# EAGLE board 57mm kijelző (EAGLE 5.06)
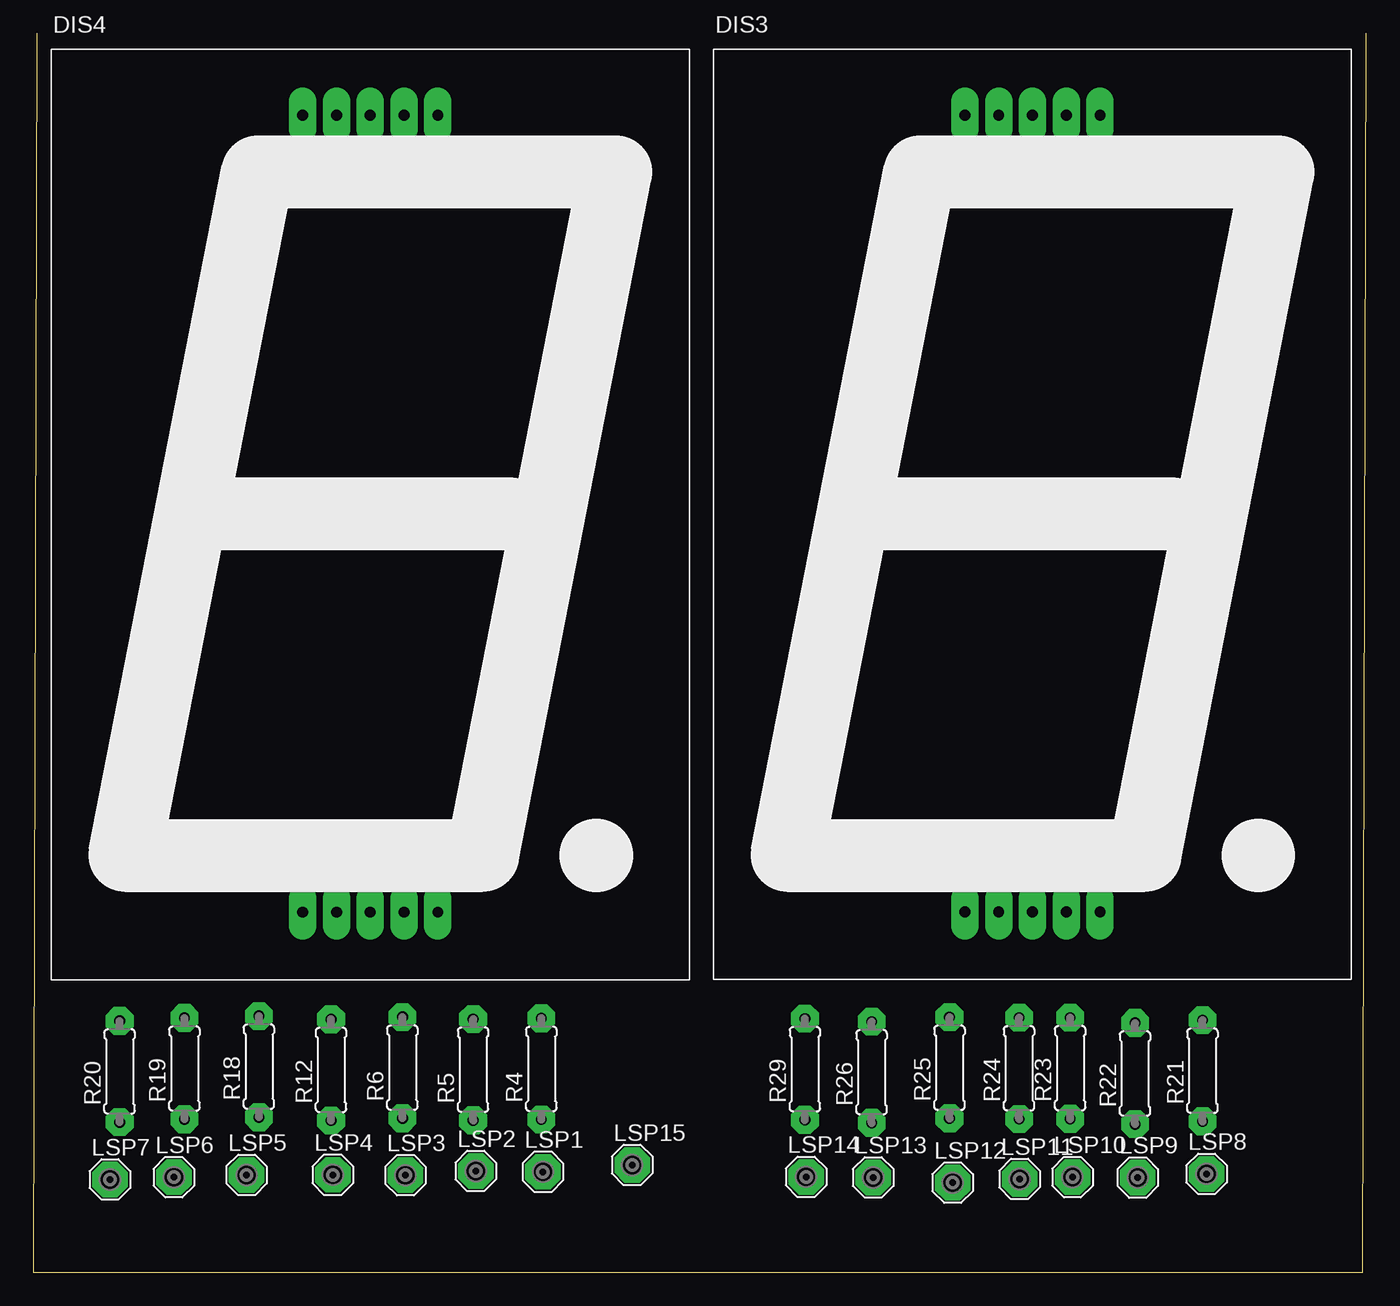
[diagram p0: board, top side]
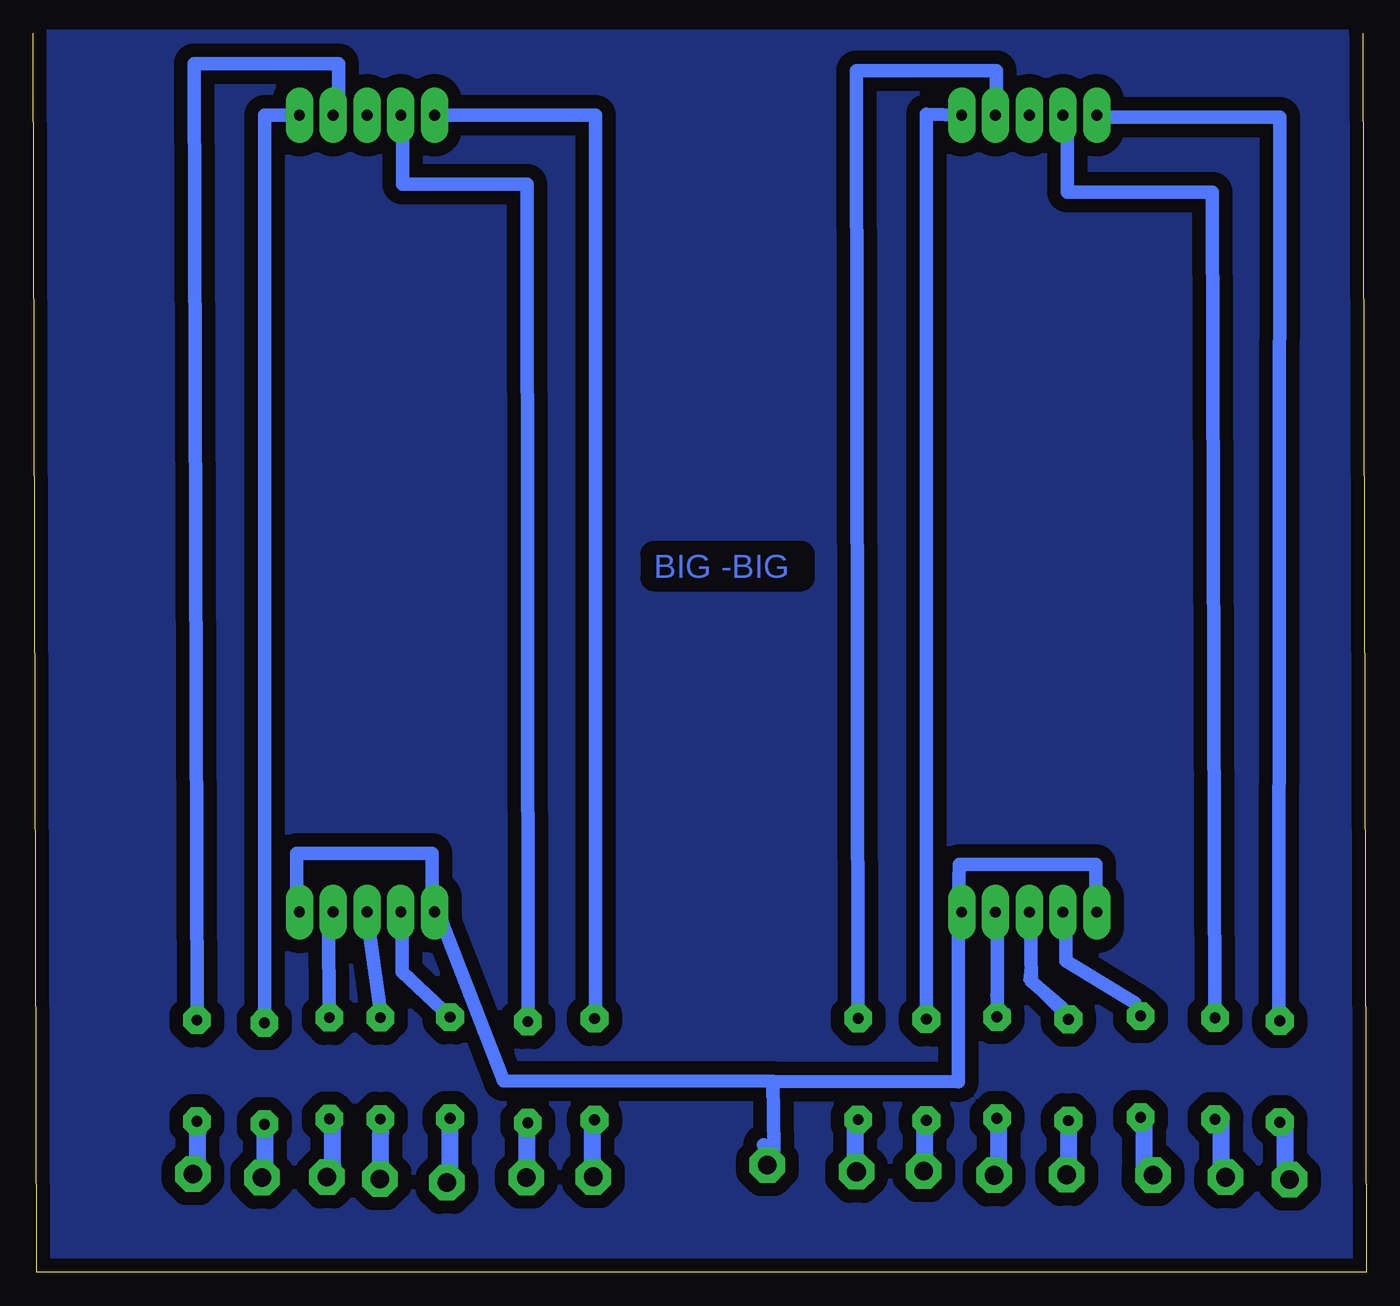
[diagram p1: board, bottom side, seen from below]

Size 100.27 x 93.21 mm. Coordinates in mm from the lower left corner, seen from the top.
Outline: 100.27,93.21 100,0 0,0 0.27,93.21
Copper layers (1*16): Top 0.035mm / dielectric 1.5mm / Bottom 0.035mm
Design rules "default *": minimum track width 10mil, minimum drill 10mil, track to track 40mil, track to pad 40mil, pad to pad 40mil, via to via 40mil, smd to smd 8mil, copper to edge 40mil, drill to drill 8mil, minimum pad ring 25mil, minimum via ring 8mil, stop-mask expansion 4mil, vias tented up to drill 0mil, thermal gap 10mil

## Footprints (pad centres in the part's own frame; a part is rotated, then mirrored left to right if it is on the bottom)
SX23-XX = drill 0.813 long: 1 18.923,5.08; 2 21.463,5.08; 3 24.003,5.08; 4 26.543,5.08; 5 29.083,5.08; 6 29.083,65.024; 7 26.543,65.024; 8 24.003,65.024; 9 21.463,65.024; 10 18.923,65.024
SE14 = drill 1.397 pad 2.54 octagon: MP 0,0
0207/7 = drill 0.813 octagon: 1 -3.81,0; 2 3.81,0

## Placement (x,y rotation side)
DIS3  SA23-11  [SX23-XX]  51.16,22.03 0 top
DIS4  SA23-11  [SX23-XX]  1.35,22.03 0 top
LSP1  SE14  [SE14]  38.35,7.57 0 top
LSP2  SE14  [SE14]  33.29,7.63 0 top
LSP3  SE14  [SE14]  28,7.31 0 top
LSP4  SE14  [SE14]  22.53,7.34 0 top
LSP5  SE14  [SE14]  16.05,7.34 0 top
LSP6  SE14  [SE14]  10.58,7.16 0 top
LSP7  SE14  [SE14]  5.77,6.99 0 top
LSP8  SE14  [SE14]  88.26,7.41 0 top
LSP9  SE14  [SE14]  83.08,7.14 0 top
LSP10  SE14  [SE14]  78.17,7.17 0 top
LSP11  SE14  [SE14]  74.19,7.03 0 top
LSP12  SE14  [SE14]  69.16,6.75 0 top
LSP13  SE14  [SE14]  63.18,7.15 0 top
LSP14  SE14  [SE14]  58.13,7.19 0 top
LSP15  SE14  [SE14]  45.04,8.08 0 top
R4  [0207/7]  38.22,15.31 90 top
R5  [0207/7]  33.09,15.25 90 top
R6  [0207/7]  27.77,15.41 90 top
R12  [0207/7]  22.4,15.23 90 top
R18  [0207/7]  16.98,15.48 90 top
R19  [0207/7]  11.38,15.33 90 top
R20  [0207/7]  6.5,15.11 90 top
R21  [0207/7]  87.95,15.17 90 top
R22  [0207/7]  82.88,14.96 90 top
R23  [0207/7]  78,15.36 90 top
R24  [0207/7]  74.15,15.35 90 top
R25  [0207/7]  68.92,15.4 90 top
R26  [0207/7]  63.06,15.06 90 top
R29  [0207/7]  58.04,15.29 90 top

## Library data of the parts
DIS3 DIS4 = display-kingbright
LSP1-LSP15 = solpad
R4-R6 R12 R18-R26 R29 = rcl

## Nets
N$1: LSP1.MP R4.1
N$3: DIS4.8
N$4: DIS3.8
N$5: LSP2.MP R5.1
N$6: LSP3.MP R6.1
N$7: LSP4.MP R12.1
N$8: DIS3.3 R24.2
N$10: LSP5.MP R18.1
N$11: LSP6.MP R19.1
N$12: DIS4.6 R5.2
N$13: LSP7.MP R20.1
N$14: LSP8.MP R21.1
N$15: LSP9.MP R22.1
N$16: LSP10.MP R23.1
N$17: LSP11.MP R24.1
N$22: LSP12.MP R25.1
N$23: LSP13.MP R26.1
N$24: DIS3.2 R25.2
N$25: DIS3.9 R26.2
N$26: LSP14.MP R29.1
N$27: DIS3.1 DIS3.5 DIS4.1 DIS4.5 LSP15.MP
N$30: DIS3.10 R29.2
N$31: DIS4.7 R4.2
N$33: DIS4.3 R12.2
N$37: DIS4.2 R18.2
N$39: DIS4.9 R19.2
N$42: DIS4.4 R6.2
N$44: DIS4.10 R20.2
N$46: DIS3.6 R22.2
N$48: DIS3.4 R23.2
N$83: DIS3.7 R21.2

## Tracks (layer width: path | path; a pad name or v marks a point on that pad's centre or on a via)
N$1
  Bottom 0.254: 38.41,11.67 38.37,11.79 R4.1 | LSP1.MP 38.41,7.86
  Bottom 1.27: 38.41,7.86 38.41,11.67
N$2
  pour Bottom: 30.73,82.92 24.72,82.79 24.6,78.59 19.8,78.59 19.93,76.78 19.98,76.21 20.02,34.29 29.9,34.29 29.9,34.03 30.43,34.03
N$5
  Bottom 0.254: 33.21,11.48 33.29,11.79 R5.1 | LSP2.MP 33.21,7.67
  Bottom 1.27: 33.21,7.67 33.21,11.48
N$6
  Bottom 0.254: 27.65,11.61 R6.1 | LSP3.MP 27.65,7.8
  Bottom 1.27: 27.65,7.8 27.65,11.61
N$7
  Bottom 0.254: 22.38,11.3 R12.1 | LSP4.MP 22.38,7.48
  Bottom 1.27: 22.38,7.48 22.38,11.3
N$8
  Bottom 0.254: R24.2 74.14,19.56 | 75.2,27.03 DIS3.3
  Bottom 1.016: 74.14,19.56 75.2,27.03
N$10
  Bottom 0.254: 16.7,11.54 16.78,11.79 R18.1 | LSP5.MP 16.7,7.73
  Bottom 1.27: 16.7,7.73 16.7,11.54
N$11
  Bottom 0.254: 10.89,11.61 R19.1 | 10.89,6.53 LSP6.MP
  Bottom 1.27: 10.89,6.53 10.89,11.61
N$12
  Bottom 1.016: DIS4.6 33.09,87.13 R5.2
N$13
  Bottom 0.254: 6.1,10.71 6.62,10.52 R20.1 | LSP7.MP 6.1,8.17
  Bottom 1.27: 6.1,8.17 6.1,10.71
N$14
  Bottom 0.254: 87.9,10.52 R21.1 | LSP8.MP 87.9,7.98
  Bottom 1.27: 87.9,7.98 87.9,10.52
N$15
  Bottom 0.254: 82.82,10.52 R22.1 | LSP9.MP 82.82,7.98
  Bottom 1.27: 82.82,7.98 82.82,10.52
N$16
  Bottom 0.254: 77.74,11.79 R23.1 | LSP10.MP 77.74,7.98
  Bottom 1.27: 77.74,7.98 77.74,11.79
N$17
  Bottom 0.254: 74.14,10.52 73.93,11.79 R24.1 | LSP11.MP 74.14,6.71
  Bottom 1.27: 74.14,6.71 74.14,10.52
N$18
  pour Bottom: 75.03,83.51 75.03,80.02 69.01,80.02 69.01,79.71 68.85,79.71 68.85,34.21 80.73,34.21 80.74,83.52
N$19
  pour Bottom: 99.75,93.3 0.58,93.3 0.58,92.67 0.27,92.67 0.27,0.6 99.9,0.6 99.9,92.67
N$22
  Bottom 0.254: 68.93,10.65 68.85,11.79 R25.1 | LSP12.MP 68.93,6.84
  Bottom 1.27: 68.93,6.84 68.93,10.65
N$23
  Bottom 0.254: 63.12,10.52 R26.1 | LSP13.MP 63.12,7.98
  Bottom 1.27: 63.12,7.98 63.12,10.52
N$24
  Bottom 0.406: 72.46,27.11 DIS3.2
  Bottom 1.016: 72.46,27.11 72.51,26.75 72.53,22.61 R25.2
N$25
  Bottom 0.406: 72.49,87.05 DIS3.9
  Bottom 1.016: 72.49,87.05 72.49,81.88 63.14,81.88 R26.2
N$26
  Bottom 0.254: 58.19,11.42 R29.1 | LSP14.MP 58.19,7.61
  Bottom 1.27: 58.19,7.61 58.19,11.42
N$27
  Bottom 0.254: 80.29,26.94 80.41,26.73 80.3,27.2 80.12,27.16 | DIS3.5 80.01,27.39 | LSP15.MP 44.72,9.25 44.57,9.27
  Bottom 0.406: 20.32,26.92 DIS4.1 | 30.69,28.33 30.16,28.87 DIS4.5 30.67,26.92 | 80.45,27.11 DIS3.5 | 70.28,27.51 70.08,27.51 DIS3.1
  Bottom 1.016: 80.29,26.94 80.23,26.79 80.14,26.88 | 80.01,27.39 80,26.09 80.36,25.8 80.3,27.2 | 20.32,26.92 20.32,30.69 30.6,30.69 30.69,28.33 | 30.67,26.92 30.67,16.65 30.66,14.33 44.61,14.37 | 44.61,14.37 44.57,9.27 45.33,9.58 | 80.45,27.11 80.45,31.54 70.28,31.54 70.28,27.51 | DIS3.1 69.76,27 64.89,14.42 44.61,14.37
N$30
  Bottom 0.406: R29.2 57.99,19.28 | 70.08,87.07 DIS3.10
  Bottom 1.016: 57.99,19.28 57.98,87.07 70.08,87.07
N$31
  Bottom 0.406: 27.83,86.87 DIS4.7
  Bottom 1.016: 27.83,86.87 27.83,90.39 38.34,90.39 R4.2
N$33
  Bottom 0.254: R12.2 23.13,19.41 25.67,21.95 25.19,26.28
  Bottom 1.016: 22.88,19.96 25.19,21.9 25.26,26.44 25.19,26.28 DIS4.3
N$37
  Bottom 0.406: R18.2 17.4,20.28
  Bottom 1.016: 17.4,20.28 22.59,23.43 22.59,27.11 DIS4.2
N$39
  Bottom 0.406: 22.49,86.87 DIS4.9
  Bottom 1.016: 22.49,86.87 22.49,81.24 11.56,81.24 R19.2
N$42
  Bottom 0.406: R6.2 26.95,19.69 27.6,19.61 | 27.75,26.74 DIS4.4
  Bottom 1.016: 27.6,19.61 27.76,19.61 27.76,20.83 27.8,20.83 27.8,20.87 27.76,20.87 27.76,20.36 27.75,26.74
N$44
  Bottom 0.406: R20.2 6.59,19.96 | 20,86.9 DIS4.10
  Bottom 1.016: 6.59,19.96 6.52,86.9 20,86.9
N$46
  Bottom 1.016: DIS3.6 82.88,87.05 R22.2
N$48
  Bottom 0.254: 77.74,27.03 DIS3.4
  Bottom 1.016: 77.74,27.03 78.05,26.37 R23.2
N$83
  Bottom 0.406: 77.3,87.05 DIS3.7
  Bottom 1.016: 77.3,87.05 77.3,90.93 88.16,90.93 R21.2

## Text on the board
Bottom: BIG -BIG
